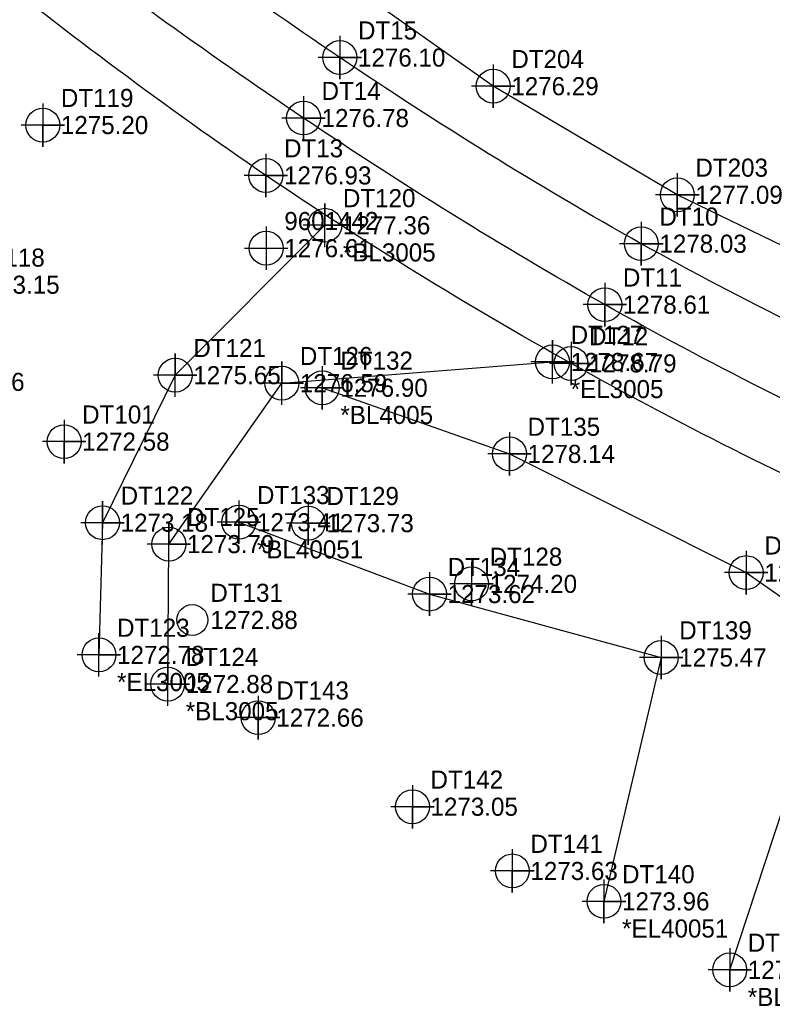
# Model space of a CAD drawing. Extents: x 1391270 to 1392151, y 960049 to 960667.
# Drawn here: x 1391741.8 to 1391845.8, y 960082.4 to 960218.7 of the extents above; entities that cross this region are included whole.
import ezdxf

# ---------------------------------------------------------------- set-up
doc = ezdxf.new("R2010")
doc.units = 0
for name, color, linetype in [('Cogo Default Point CELL', 7, 'Continuous'), ('COGO Default Point Elevation', 7, 'Continuous'), ('COGO Default Point Number', 7, 'Continuous'), ('Exist DTM Breakline', 7, 'Continuous'), ('Exist DTM Breakline Cogo Comment', 7, 'Continuous'), ('Exist DTM Breakline Cogo Elevation', 7, 'Continuous'), ('Exist DTM Breakline Cogo Number', 7, 'Continuous'), ('Exist DTM Breakline Cogo Point CELL', 7, 'Continuous'), ('Exist DTM Crownline', 7, 'Continuous'), ('Exist DTM Crownline Cogo Elevation', 7, 'Continuous'), ('Exist DTM Crownline Cogo Number', 7, 'Continuous'), ('Exist DTM Crownline Cogo Point CELL', 7, 'Continuous'), ('Exist DTM Regular Point CELL', 7, 'Continuous'), ('Exist DTM Regular Point Cogo Elevation', 7, 'Continuous'), ('Exist DTM Regular Point Cogo Number', 7, 'Continuous'), ('Exist Other Culture Well CELL', 7, 'Continuous'), ('Exist Other Culture Well Cogo Elevation', 7, 'Continuous'), ('Exist Other Culture Well Cogo Number', 7, 'Continuous'), ('Exist Roads EOP', 7, 'Continuous'), ('Exist Roads EOP Cogo Elevation', 7, 'Continuous'), ('Exist Roads EOP Cogo Number', 7, 'Continuous'), ('Exist Roads EOP Cogo Point CELL', 7, 'Continuous'), ('Exist Roads EOP Other', 7, 'Continuous'), ('Exist Roads EOP Other Cogo Comment', 7, 'Continuous'), ('Exist Roads EOP Other Cogo Elevation', 7, 'Continuous'), ('Exist Roads EOP Other Cogo Number', 7, 'Continuous'), ('Exist Roads EOP Other Cogo Point CELL', 7, 'Continuous'), ('Exist Roads Soil', 7, 'Continuous'), ('Exist Roads Soil Cogo Comment', 7, 'Continuous'), ('Exist Roads Soil Cogo Elevation', 7, 'Continuous'), ('Exist Roads Soil Cogo Number', 7, 'Continuous'), ('Exist Roads Soil Cogo Point CELL', 7, 'Continuous'), ('Exist Vegetation Tree Cogo Elevation', 7, 'Continuous'), ('Exist Vegetation Tree Cogo Number', 7, 'Continuous')]:
    doc.layers.add(name, color=color, linetype=linetype)

msp = doc.modelspace()

# ---------------------------------------------------------------- linework, layer by layer
at = {"layer": 'Cogo Default Point CELL'}
for points in [[(1391775.844, 960190.147), (1391775.844, 960187.147)], [(1391772.844, 960187.147), (1391775.844, 960187.147)], [(1391775.844, 960187.147), (1391778.844, 960187.147)], [(1391775.844, 960187.147), (1391775.844, 960184.147)]]:
    msp.add_lwpolyline(points, dxfattribs=at)
msp.add_circle((1391775.844, 960187.147), 2.344, dxfattribs=at)
at = {"layer": 'Exist DTM Breakline'}
for points in [[(1391918.848, 960154.955), (1391875.094, 960173.971), (1391832.683, 960194.523), (1391807.232, 960209.528), (1391789.699, 960221.943), (1391750.487, 960246.736), (1391714.022, 960278.792), (1391697.218, 960295.108)], [(1391783.595, 960167.857), (1391809.479, 960158.717), (1391842.214, 960142.313), (1391852.279, 960135.283), (1391849.414, 960127.307)], [(1391772.064, 960149.278), (1391798.423, 960139.354), (1391830.446, 960130.587), (1391822.546, 960096.889)]]:
    msp.add_lwpolyline(points, dxfattribs=at)
at = {"layer": 'Exist DTM Breakline Cogo Point CELL'}
for points in [[(1391807.232, 960212.528), (1391807.232, 960206.528), (1391807.232, 960209.528), (1391810.232, 960209.528), (1391804.232, 960209.528)], [(1391832.683, 960197.523), (1391832.683, 960191.523), (1391832.683, 960194.523), (1391835.683, 960194.523), (1391829.683, 960194.523)], [(1391783.595, 960170.857), (1391783.595, 960164.857), (1391783.595, 960167.857), (1391786.595, 960167.857), (1391780.595, 960167.857)], [(1391809.479, 960161.717), (1391809.479, 960155.717), (1391809.479, 960158.717), (1391812.479, 960158.717), (1391806.479, 960158.717)], [(1391772.064, 960152.278), (1391772.064, 960146.278), (1391772.064, 960149.278), (1391775.064, 960149.278), (1391769.064, 960149.278)], [(1391842.214, 960145.313), (1391842.214, 960139.313), (1391842.214, 960142.313), (1391845.214, 960142.313), (1391839.214, 960142.313)], [(1391798.423, 960142.354), (1391798.423, 960136.354), (1391798.423, 960139.354), (1391801.423, 960139.354), (1391795.423, 960139.354)], [(1391830.446, 960133.587), (1391830.446, 960127.587), (1391830.446, 960130.587), (1391833.446, 960130.587), (1391827.446, 960130.587)], [(1391822.546, 960099.889), (1391822.546, 960093.889), (1391822.546, 960096.889), (1391825.546, 960096.889), (1391819.546, 960096.889)]]:
    msp.add_lwpolyline(points, dxfattribs=at)
for centre in [(1391807.232, 960209.528), (1391832.683, 960194.523), (1391783.595, 960167.857), (1391809.479, 960158.717), (1391772.064, 960149.278), (1391842.214, 960142.313), (1391798.423, 960139.354), (1391830.446, 960130.587), (1391822.546, 960096.889)]:
    msp.add_circle(centre, 2.344, dxfattribs=at)
at = {"layer": 'Exist DTM Crownline'}
msp.add_spline([(1391912.281, 960138.966), (1391866.83, 960157.169), (1391822.661, 960179.344), (1391780.998, 960205.13), (1391740.996, 960234.086), (1391702.853, 960265.768), (1391666.471, 960297.967)], degree=3, dxfattribs=at)
at = {"layer": 'Exist DTM Crownline Cogo Point CELL'}
for points in [[(1391780.998, 960208.13), (1391780.998, 960202.13), (1391780.998, 960205.13), (1391783.998, 960205.13), (1391777.998, 960205.13)], [(1391822.661, 960182.344), (1391822.661, 960176.344), (1391822.661, 960179.344), (1391825.661, 960179.344), (1391819.661, 960179.344)]]:
    msp.add_lwpolyline(points, dxfattribs=at)
for centre in [(1391780.998, 960205.13), (1391822.661, 960179.344)]:
    msp.add_circle(centre, 2.344, dxfattribs=at)
at = {"layer": 'Exist DTM Regular Point CELL'}
for points in [[(1391744.953, 960207.158), (1391744.953, 960201.158), (1391744.953, 960204.158), (1391747.953, 960204.158), (1391741.953, 960204.158)], [(1391747.897, 960163.412), (1391747.897, 960157.412), (1391747.897, 960160.412), (1391750.897, 960160.412), (1391744.897, 960160.412)], [(1391781.663, 960152.15), (1391781.663, 960146.15), (1391781.663, 960149.15), (1391784.663, 960149.15), (1391778.663, 960149.15)], [(1391804.244, 960143.762), (1391804.244, 960137.762), (1391804.244, 960140.762), (1391807.244, 960140.762), (1391801.244, 960140.762)], [(1391774.739, 960125.274), (1391774.739, 960119.274), (1391774.739, 960122.274), (1391777.739, 960122.274), (1391771.739, 960122.274)], [(1391796.059, 960112.965), (1391796.059, 960106.965), (1391796.059, 960109.965), (1391799.059, 960109.965), (1391793.059, 960109.965)], [(1391809.872, 960104.089), (1391809.872, 960098.089), (1391809.872, 960101.089), (1391812.872, 960101.089), (1391806.872, 960101.089)]]:
    msp.add_lwpolyline(points, dxfattribs=at)
for centre in [(1391744.953, 960204.158), (1391747.897, 960160.412), (1391781.663, 960149.15), (1391804.244, 960140.762), (1391774.739, 960122.274), (1391796.059, 960109.965), (1391809.872, 960101.089)]:
    msp.add_circle(centre, 2.344, dxfattribs=at)
at = {"layer": 'Exist Other Culture Well CELL'}
msp.add_circle((1391765.625, 960135.779), 2.132, dxfattribs=at)
at = {"layer": 'Exist Roads EOP'}
for points in [[(1391915.673, 960148.156), (1391871.111, 960166.209), (1391827.705, 960187.765), (1391786.031, 960213.485), (1391746.988, 960241.829), (1391709.378, 960273.178), (1391672.886, 960305.161)], [(1391909.259, 960130.384), (1391863.262, 960148.577), (1391817.991, 960171.223), (1391775.806, 960197.201), (1391735.389, 960227.09), (1391696.713, 960258.946), (1391660.088, 960291.389)]]:
    msp.add_spline(points, degree=3, dxfattribs=at)
at = {"layer": 'Exist Roads EOP Cogo Point CELL'}
for points in [[(1391786.031, 960216.485), (1391786.031, 960210.485), (1391786.031, 960213.485), (1391789.031, 960213.485), (1391783.031, 960213.485)], [(1391775.806, 960200.201), (1391775.806, 960194.201), (1391775.806, 960197.201), (1391778.806, 960197.201), (1391772.806, 960197.201)], [(1391827.705, 960190.765), (1391827.705, 960184.765), (1391827.705, 960187.765), (1391830.705, 960187.765), (1391824.705, 960187.765)], [(1391817.991, 960174.223), (1391817.991, 960168.223), (1391817.991, 960171.223), (1391820.991, 960171.223), (1391814.991, 960171.223)]]:
    msp.add_lwpolyline(points, dxfattribs=at)
for centre in [(1391786.031, 960213.485), (1391775.806, 960197.201), (1391827.705, 960187.765), (1391817.991, 960171.223)]:
    msp.add_circle(centre, 2.344, dxfattribs=at)
at = {"layer": 'Exist Roads EOP Other'}
msp.add_lwpolyline([(1391839.93, 960087.426), (1391849.786, 960117.376), (1391856.383, 960137.584), (1391857.314, 960142.252), (1391856.722, 960151.227)], dxfattribs=at)
at = {"layer": 'Exist Roads EOP Other Cogo Point CELL'}
msp.add_lwpolyline([(1391839.93, 960090.426), (1391839.93, 960084.426), (1391839.93, 960087.426), (1391842.93, 960087.426), (1391836.93, 960087.426)], dxfattribs=at)
msp.add_circle((1391839.93, 960087.426), 2.344, dxfattribs=at)
at = {"layer": 'Exist Roads Soil'}
for points in [[(1391783.948, 960190.309), (1391763.27, 960169.596), (1391753.219, 960149.21), (1391752.721, 960130.944)], [(1391762.223, 960126.914), (1391762.395, 960146.254), (1391777.996, 960168.496), (1391815.442, 960171.425)]]:
    msp.add_lwpolyline(points, dxfattribs=at)
at = {"layer": 'Exist Roads Soil Cogo Point CELL'}
for points in [[(1391783.948, 960187.309), (1391783.948, 960193.309), (1391783.948, 960190.309), (1391786.948, 960190.309), (1391780.948, 960190.309)], [(1391815.442, 960168.425), (1391815.442, 960174.425), (1391815.442, 960171.425), (1391818.442, 960171.425), (1391812.442, 960171.425)], [(1391763.27, 960166.596), (1391763.27, 960172.596), (1391763.27, 960169.596), (1391766.27, 960169.596), (1391760.27, 960169.596)], [(1391777.996, 960165.496), (1391777.996, 960171.496), (1391777.996, 960168.496), (1391780.996, 960168.496), (1391774.996, 960168.496)], [(1391753.219, 960146.21), (1391753.219, 960152.21), (1391753.219, 960149.21), (1391756.219, 960149.21), (1391750.219, 960149.21)], [(1391762.395, 960143.254), (1391762.395, 960149.254), (1391762.395, 960146.254), (1391765.395, 960146.254), (1391759.395, 960146.254)], [(1391752.721, 960127.944), (1391752.721, 960133.944), (1391752.721, 960130.944), (1391755.721, 960130.944), (1391749.721, 960130.944)], [(1391762.223, 960123.914), (1391762.223, 960129.914), (1391762.223, 960126.914), (1391765.223, 960126.914), (1391759.223, 960126.914)]]:
    msp.add_lwpolyline(points, dxfattribs=at)
for centre in [(1391783.948, 960190.309), (1391815.442, 960171.425), (1391763.27, 960169.596), (1391777.996, 960168.496), (1391753.219, 960149.21), (1391762.395, 960146.254), (1391752.721, 960130.944), (1391762.223, 960126.914)]:
    msp.add_circle(centre, 2.344, dxfattribs=at)

# ---------------------------------------------------------------- texts
at = {"layer": 'COGO Default Point Elevation'}
msp.add_text('1276.61', height=2.5, dxfattribs=at).set_placement((1391778.344, 960185.897))
at = {"layer": 'COGO Default Point Number'}
msp.add_text('9601442', height=2.5, dxfattribs=at).set_placement((1391778.344, 960189.647))
at = {"layer": 'Exist DTM Breakline Cogo Comment'}
for s, p in [('*BL4005', (1391786.095, 960162.857)), ('*BL40051', (1391774.564, 960144.278)), ('*EL40051', (1391825.046, 960091.889))]:
    msp.add_text(s, height=2.5, dxfattribs=at).set_placement(p)
at = {"layer": 'Exist DTM Breakline Cogo Elevation'}
for s, p in [('1276.29', (1391809.732, 960208.278)), ('1277.09', (1391835.183, 960193.273)), ('1276.90', (1391786.095, 960166.607)), ('1278.14', (1391811.979, 960157.467)), ('1273.41', (1391774.564, 960148.028)), ('1279.27', (1391844.714, 960141.063)), ('1273.62', (1391800.923, 960138.104)), ('1275.47', (1391832.946, 960129.337)), ('1273.96', (1391825.046, 960095.639))]:
    msp.add_text(s, height=2.5, dxfattribs=at).set_placement(p)
at = {"layer": 'Exist DTM Breakline Cogo Number'}
for s, p in [('DT204', (1391809.732, 960212.028)), ('DT203', (1391835.183, 960197.023)), ('DT132', (1391786.095, 960170.357)), ('DT135', (1391811.979, 960161.217)), ('DT133', (1391774.564, 960151.778)), ('DT136', (1391844.714, 960144.813)), ('DT134', (1391800.923, 960141.854)), ('DT139', (1391832.946, 960133.087)), ('DT140', (1391825.046, 960099.389))]:
    msp.add_text(s, height=2.5, dxfattribs=at).set_placement(p)
at = {"layer": 'Exist DTM Crownline Cogo Elevation'}
for s, p in [('1276.78', (1391783.498, 960203.88)), ('1278.61', (1391825.161, 960178.094))]:
    msp.add_text(s, height=2.5, dxfattribs=at).set_placement(p)
at = {"layer": 'Exist DTM Crownline Cogo Number'}
for s, p in [('DT14', (1391783.498, 960207.63)), ('DT11', (1391825.161, 960181.844))]:
    msp.add_text(s, height=2.5, dxfattribs=at).set_placement(p)
at = {"layer": 'Exist DTM Regular Point Cogo Elevation'}
for s, p in [('1275.20', (1391747.453, 960202.908)), ('1273.15', (1391735.196, 960180.848)), ('1271.16', (1391730.351, 960167.425)), ('1272.66', (1391777.239, 960121.024)), ('1273.05', (1391798.559, 960108.715)), ('1273.63', (1391812.372, 960099.839))]:
    msp.add_text(s, height=2.5, dxfattribs=at).set_placement(p)
at = {"layer": 'Exist DTM Regular Point Cogo Number'}
for s, p in [('DT119', (1391747.453, 960206.658)), ('DT118', (1391735.196, 960184.598)), ('DT143', (1391777.239, 960124.774)), ('DT142', (1391798.559, 960112.465)), ('DT141', (1391812.372, 960103.589))]:
    msp.add_text(s, height=2.5, dxfattribs=at).set_placement(p)
at = {"layer": 'Exist Other Culture Well Cogo Elevation'}
msp.add_text('1272.88', height=2.5, dxfattribs=at).set_placement((1391768.121, 960134.525))
at = {"layer": 'Exist Other Culture Well Cogo Number'}
msp.add_text('DT131', height=2.5, dxfattribs=at).set_placement((1391768.121, 960138.275))
at = {"layer": 'Exist Roads EOP Cogo Elevation'}
for s, p in [('1276.10', (1391788.531, 960212.235)), ('1276.93', (1391778.306, 960195.951)), ('1278.03', (1391830.205, 960186.515)), ('1278.79', (1391820.491, 960169.973))]:
    msp.add_text(s, height=2.5, dxfattribs=at).set_placement(p)
at = {"layer": 'Exist Roads EOP Cogo Number'}
for s, p in [('DT15', (1391788.531, 960215.985)), ('DT13', (1391778.306, 960199.701)), ('DT10', (1391830.205, 960190.265)), ('DT12', (1391820.491, 960173.723))]:
    msp.add_text(s, height=2.5, dxfattribs=at).set_placement(p)
at = {"layer": 'Exist Roads EOP Other Cogo Comment'}
msp.add_text('*BL3003', height=2.5, dxfattribs=at).set_placement((1391842.43, 960082.426))
at = {"layer": 'Exist Roads EOP Other Cogo Elevation'}
msp.add_text('1275.61', height=2.5, dxfattribs=at).set_placement((1391842.43, 960086.176))
at = {"layer": 'Exist Roads EOP Other Cogo Number'}
msp.add_text('DT144', height=2.5, dxfattribs=at).set_placement((1391842.43, 960089.926))
at = {"layer": 'Exist Roads Soil Cogo Comment'}
for s, p in [('*BL3005', (1391786.448, 960185.309)), ('*EL3005', (1391817.942, 960166.425)), ('*EL3005', (1391755.221, 960125.944)), ('*BL3005', (1391764.723, 960121.914))]:
    msp.add_text(s, height=2.5, dxfattribs=at).set_placement(p)
at = {"layer": 'Exist Roads Soil Cogo Elevation'}
for s, p in [('1277.36', (1391786.448, 960189.059)), ('1278.67', (1391817.942, 960170.175)), ('1275.65', (1391765.77, 960168.346)), ('1276.59', (1391780.496, 960167.246)), ('1273.18', (1391755.719, 960147.96)), ('1273.79', (1391764.895, 960145.004)), ('1272.78', (1391755.221, 960129.694)), ('1272.88', (1391764.723, 960125.664))]:
    msp.add_text(s, height=2.5, dxfattribs=at).set_placement(p)
at = {"layer": 'Exist Roads Soil Cogo Number'}
for s, p in [('DT120', (1391786.448, 960192.809)), ('DT127', (1391817.942, 960173.925)), ('DT121', (1391765.77, 960172.096)), ('DT126', (1391780.496, 960170.996)), ('DT122', (1391755.719, 960151.71)), ('DT125', (1391764.895, 960148.754)), ('DT123', (1391755.221, 960133.444)), ('DT124', (1391764.723, 960129.414))]:
    msp.add_text(s, height=2.5, dxfattribs=at).set_placement(p)
at = {"layer": 'Exist Vegetation Tree Cogo Elevation'}
for s, p in [('1272.58', (1391750.397, 960159.162)), ('1273.73', (1391784.163, 960147.9)), ('1274.20', (1391806.744, 960139.512))]:
    msp.add_text(s, height=2.5, dxfattribs=at).set_placement(p)
at = {"layer": 'Exist Vegetation Tree Cogo Number'}
for s, p in [('DT101', (1391750.397, 960162.912)), ('DT129', (1391784.163, 960151.65)), ('DT128', (1391806.744, 960143.262))]:
    msp.add_text(s, height=2.5, dxfattribs=at).set_placement(p)

doc.saveas('drawing.dxf')
